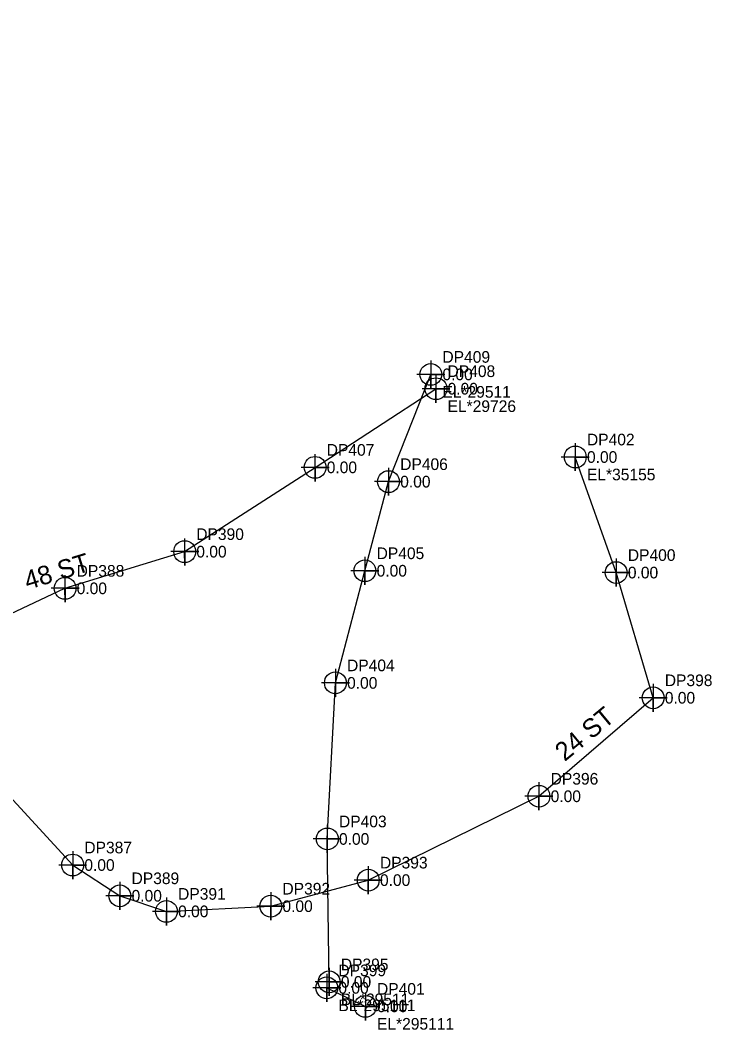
# Model space of a CAD drawing. Extents: x 1182504 to 1186036, y 573002 to 575111.
# Drawn here: x 1184140 to 1184288.3, y 573087.8 to 573304.5 of the extents above; entities that cross this region are included whole.
import ezdxf

# ---------------------------------------------------------------- set-up
doc = ezdxf.new("R2010")
doc.units = 0
for name, color, linetype in [('Exist Utilities Power UG Cable SUE LOS B', 7, 'Continuous'), ('Exist Utilities Power UG Cable SUE LOS B Cogo Comment', 7, 'Continuous'), ('Exist Utilities Power UG Cable SUE LOS B Cogo Elevation', 7, 'Continuous'), ('Exist Utilities Power UG Cable SUE LOS B Cogo Number', 7, 'Continuous'), ('Exist Utilities Power UG Cable SUE LOS B Cogo Point CELL', 7, 'Continuous'), ('Exist Utilities Telephone UG Conduit SUE LOS B', 7, 'Continuous'), ('Exist Utilities Telephone UG Conduit SUE LOS B Cogo Comment', 7, 'Continuous'), ('Exist Utilities Telephone UG Conduit SUE LOS B Cogo Elevation', 7, 'Continuous'), ('Exist Utilities Telephone UG Conduit SUE LOS B Cogo Number', 7, 'Continuous'), ('Exist Utilities Telephone UG Conduit SUE LOS B Cogo Point CELL', 7, 'Continuous'), ('Exist Utilities Telephone UG Conduit SUE LOS B Text', 7, 'Continuous'), ('Exist Utilities Telephone UG FO SUE LOS C', 7, 'Continuous'), ('Exist Utilities Telephone UG FO SUE LOS C Cogo Comment', 7, 'Continuous'), ('Exist Utilities Telephone UG FO SUE LOS C Cogo Elevation', 7, 'Continuous'), ('Exist Utilities Telephone UG FO SUE LOS C Cogo Number', 7, 'Continuous'), ('Exist Utilities Telephone UG FO SUE LOS C Cogo Point CELL', 7, 'Continuous'), ('Exist Utilities Telephone UG FO SUE LOS C Text', 7, 'Continuous')]:
    doc.layers.add(name, color=color, linetype=linetype)

msp = doc.modelspace()

# ---------------------------------------------------------------- linework, layer by layer
at = {"layer": 'Exist Utilities Power UG Cable SUE LOS B'}
msp.add_line((1184205.72, 573096.81), (1184214, 573092.84), dxfattribs=at)
msp.add_lwpolyline([(1184206.24, 573098.09), (1184205.84, 573128.77), (1184207.57, 573162.26), (1184213.91, 573186.32), (1184218.97, 573205.44), (1184228.03, 573228.46)], dxfattribs=at)
at = {"layer": 'Exist Utilities Power UG Cable SUE LOS B Cogo Point CELL'}
for points in [[(1184228.03, 573231.46), (1184228.03, 573225.46), (1184228.03, 573228.46), (1184231.03, 573228.46), (1184225.03, 573228.46)], [(1184218.97, 573208.44), (1184218.97, 573202.44), (1184218.97, 573205.44), (1184221.97, 573205.44), (1184215.97, 573205.44)], [(1184213.91, 573189.32), (1184213.91, 573183.32), (1184213.91, 573186.32), (1184216.91, 573186.32), (1184210.91, 573186.32)], [(1184207.57, 573165.26), (1184207.57, 573159.26), (1184207.57, 573162.26), (1184210.57, 573162.26), (1184204.57, 573162.26)], [(1184205.84, 573131.77), (1184205.84, 573125.77), (1184205.84, 573128.77), (1184208.84, 573128.77), (1184202.84, 573128.77)], [(1184206.24, 573101.09), (1184206.24, 573095.09), (1184206.24, 573098.09), (1184209.24, 573098.09), (1184203.24, 573098.09)], [(1184205.72, 573099.81), (1184205.72, 573093.81), (1184205.72, 573096.81), (1184208.72, 573096.81), (1184202.72, 573096.81)], [(1184214, 573095.84), (1184214, 573089.84), (1184214, 573092.84), (1184217, 573092.84), (1184211, 573092.84)]]:
    msp.add_lwpolyline(points, dxfattribs=at)
for centre in [(1184228.03, 573228.46), (1184218.97, 573205.44), (1184213.91, 573186.32), (1184207.57, 573162.26), (1184205.84, 573128.77), (1184205.72, 573096.81), (1184206.24, 573098.09), (1184214, 573092.84)]:
    msp.add_circle(centre, 2.34, dxfattribs=at)
at = {"layer": 'Exist Utilities Telephone UG Conduit SUE LOS B'}
msp.add_lwpolyline([(1184023.09, 573304.47), (1184046.48, 573279.29), (1184068.5, 573248.18), (1184095.84, 573211.96), (1184125, 573174.35), (1184127.35, 573172.14), (1184149.57, 573182.55), (1184175.23, 573190.42), (1184203.21, 573208.51), (1184229.13, 573225.39)], dxfattribs=at)
at = {"layer": 'Exist Utilities Telephone UG Conduit SUE LOS B Cogo Point CELL'}
for points in [[(1184229.11, 573228.21), (1184229.15, 573222.39), (1184229.13, 573225.39), (1184232.15, 573225.39), (1184226.15, 573225.39)], [(1184203.19, 573211.33), (1184203.22, 573205.51), (1184203.21, 573208.51), (1184206.22, 573208.51), (1184200.22, 573208.51)], [(1184175.22, 573193.23), (1184175.25, 573187.42), (1184175.23, 573190.42), (1184178.25, 573190.42), (1184172.25, 573190.42)], [(1184149.55, 573185.36), (1184149.59, 573179.55), (1184149.57, 573182.55), (1184152.59, 573182.55), (1184146.59, 573182.55)]]:
    msp.add_lwpolyline(points, dxfattribs=at)
for centre in [(1184229.15, 573225.39), (1184203.22, 573208.51), (1184175.25, 573190.42), (1184149.59, 573182.55)]:
    msp.add_circle(centre, 2.34, dxfattribs=at)
at = {"layer": 'Exist Utilities Telephone UG FO SUE LOS C'}
msp.add_lwpolyline([(1184123.17, 573153.72), (1184151.22, 573123.17), (1184161.35, 573116.57), (1184171.33, 573113.22), (1184193.71, 573114.34), (1184214.63, 573119.93), (1184251.24, 573137.93), (1184275.73, 573159.06), (1184267.8, 573185.93), (1184259.03, 573210.73)], dxfattribs=at)
at = {"layer": 'Exist Utilities Telephone UG FO SUE LOS C Cogo Point CELL'}
for points in [[(1184259.03, 573213.73), (1184259.03, 573207.73), (1184259.03, 573210.73), (1184262.03, 573210.73), (1184256.03, 573210.73)], [(1184267.8, 573188.93), (1184267.8, 573182.93), (1184267.8, 573185.93), (1184270.8, 573185.93), (1184264.8, 573185.93)], [(1184275.73, 573162.06), (1184275.73, 573156.06), (1184275.73, 573159.06), (1184278.73, 573159.06), (1184272.73, 573159.06)], [(1184251.24, 573140.93), (1184251.24, 573134.93), (1184251.24, 573137.93), (1184254.24, 573137.93), (1184248.24, 573137.93)], [(1184151.22, 573126.17), (1184151.22, 573120.17), (1184151.22, 573123.17), (1184154.22, 573123.17), (1184148.22, 573123.17)], [(1184214.63, 573122.93), (1184214.63, 573116.93), (1184214.63, 573119.93), (1184217.63, 573119.93), (1184211.63, 573119.93)], [(1184161.35, 573119.57), (1184161.35, 573113.57), (1184161.35, 573116.57), (1184164.35, 573116.57), (1184158.35, 573116.57)], [(1184171.33, 573116.22), (1184171.33, 573110.22), (1184171.33, 573113.22), (1184174.33, 573113.22), (1184168.33, 573113.22)], [(1184193.71, 573117.34), (1184193.71, 573111.34), (1184193.71, 573114.34), (1184196.71, 573114.34), (1184190.71, 573114.34)]]:
    msp.add_lwpolyline(points, dxfattribs=at)
for centre in [(1184259.03, 573210.73), (1184267.8, 573185.93), (1184275.73, 573159.06), (1184251.24, 573137.93), (1184151.22, 573123.17), (1184214.63, 573119.93), (1184161.35, 573116.57), (1184193.71, 573114.34), (1184171.33, 573113.22)]:
    msp.add_circle(centre, 2.34, dxfattribs=at)

# ---------------------------------------------------------------- texts
at = {"layer": 'Exist Utilities Power UG Cable SUE LOS B Cogo Comment'}
for s, p in [('EL*29511', (1184230.53, 573223.46)), ('BL*295111', (1184208.22, 573091.81)), ('BL*29511', (1184208.74, 573093.09)), ('EL*295111', (1184216.5, 573087.84))]:
    msp.add_text(s, height=2.5, dxfattribs=at).set_placement(p)
at = {"layer": 'Exist Utilities Power UG Cable SUE LOS B Cogo Elevation'}
for p in [(1184230.53, 573227.21), (1184221.47, 573204.19), (1184216.41, 573185.07), (1184210.07, 573161.01), (1184208.34, 573127.52), (1184208.74, 573096.84), (1184208.22, 573095.56), (1184216.5, 573091.59)]:
    msp.add_text('0.00', height=2.5, dxfattribs=at).set_placement(p)
at = {"layer": 'Exist Utilities Power UG Cable SUE LOS B Cogo Number'}
for s, p in [('DP409', (1184230.53, 573230.96)), ('DP406', (1184221.47, 573207.94)), ('DP405', (1184216.41, 573188.82)), ('DP404', (1184210.07, 573164.76)), ('DP403', (1184208.34, 573131.27)), ('DP395', (1184208.74, 573100.59)), ('DP399', (1184208.22, 573099.31)), ('DP401', (1184216.5, 573095.34))]:
    msp.add_text(s, height=2.5, dxfattribs=at).set_placement(p)
at = {"layer": 'Exist Utilities Telephone UG Conduit SUE LOS B Cogo Comment'}
msp.add_text('EL*29726', height=2.5, dxfattribs=at).set_placement((1184231.63, 573220.39))
at = {"layer": 'Exist Utilities Telephone UG Conduit SUE LOS B Cogo Elevation'}
for p in [(1184231.63, 573224.14), (1184205.71, 573207.26), (1184177.73, 573189.17), (1184152.07, 573181.3)]:
    msp.add_text('0.00', height=2.5, dxfattribs=at).set_placement(p)
at = {"layer": 'Exist Utilities Telephone UG Conduit SUE LOS B Cogo Number'}
for s, p in [('DP408', (1184231.63, 573227.89)), ('DP407', (1184205.71, 573211.01)), ('DP390', (1184177.73, 573192.92)), ('DP388', (1184152.07, 573185.05))]:
    msp.add_text(s, height=2.5, dxfattribs=at).set_placement(p)
at = {"layer": 'Exist Utilities Telephone UG Conduit SUE LOS B Text'}
msp.add_text('48 ST', height=4, rotation=17.0396, dxfattribs=at).set_placement((1184141.55, 573182.19))
at = {"layer": 'Exist Utilities Telephone UG FO SUE LOS C Cogo Comment'}
msp.add_text('EL*35155', height=2.5, dxfattribs=at).set_placement((1184261.53, 573205.73))
at = {"layer": 'Exist Utilities Telephone UG FO SUE LOS C Cogo Elevation'}
for p in [(1184261.53, 573209.48), (1184270.3, 573184.68), (1184278.23, 573157.81), (1184253.74, 573136.68), (1184153.72, 573121.92), (1184217.13, 573118.68), (1184163.85, 573115.32), (1184173.83, 573111.97), (1184196.21, 573113.09)]:
    msp.add_text('0.00', height=2.5, dxfattribs=at).set_placement(p)
at = {"layer": 'Exist Utilities Telephone UG FO SUE LOS C Cogo Number'}
for s, p in [('DP402', (1184261.53, 573213.23)), ('DP400', (1184270.3, 573188.43)), ('DP398', (1184278.23, 573161.56)), ('DP396', (1184253.74, 573140.43)), ('DP387', (1184153.72, 573125.67)), ('DP393', (1184217.13, 573122.43)), ('DP389', (1184163.85, 573119.07)), ('DP391', (1184173.83, 573115.72)), ('DP392', (1184196.21, 573116.84))]:
    msp.add_text(s, height=2.5, dxfattribs=at).set_placement(p)
at = {"layer": 'Exist Utilities Telephone UG FO SUE LOS C Text'}
msp.add_text('24 ST', height=4, rotation=39.5161, dxfattribs=at).set_placement((1184256.76, 573145.27))

doc.saveas('drawing.dxf')
